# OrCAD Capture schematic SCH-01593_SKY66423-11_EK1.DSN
size B; title: SKY66423-11 EK1 915 MHz + LC ANT Filter; rev: C2; company: Skyworks Solutions; note: SCH-01593; note: 1145 Innovation Drive, 2nd Floor; note: Ottawa, Ontario   Canada
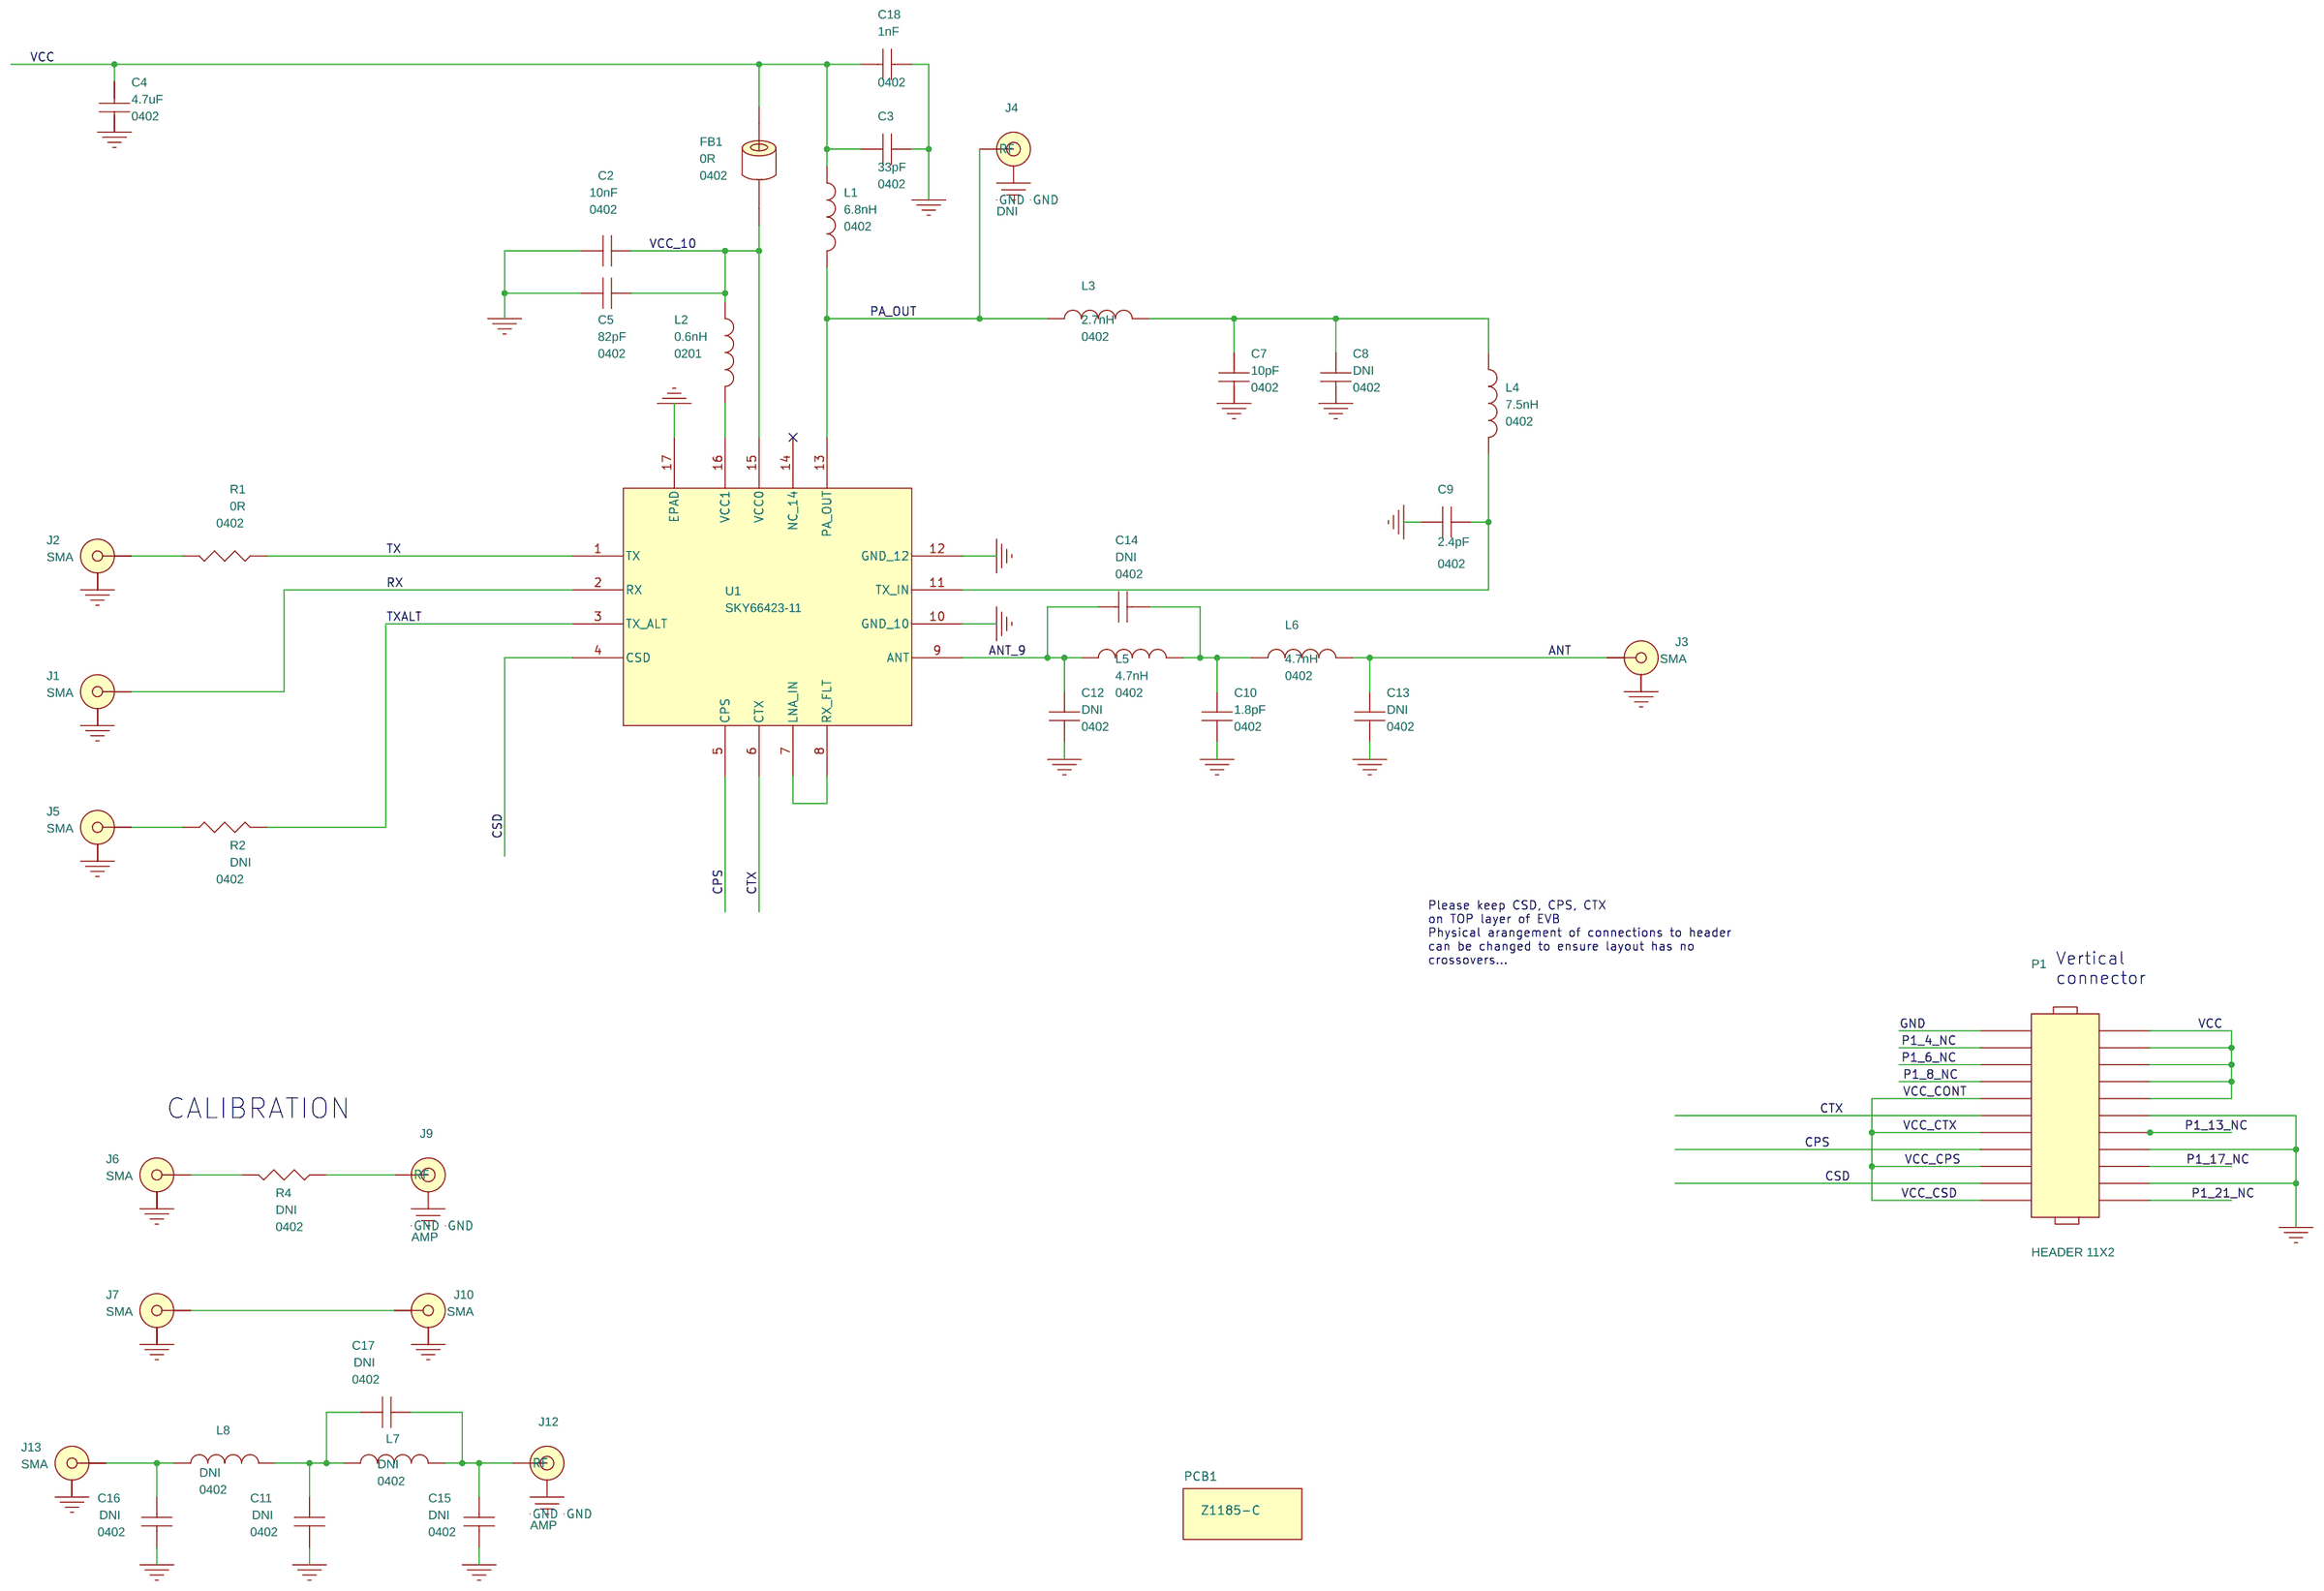
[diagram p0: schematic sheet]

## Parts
C2  10nF  [CAP_SMD_0402_1M0MX0M5M_B]
C3  33pF  [CAP_SMD_0402_1M0MX0M5M_B]
C4  4.7uF  [CAP_SMD_0402_1M0MX0M5M_B]
C5  82pF  [CAP_SMD_0402_1M0MX0M5M_B]
C7  10pF  [CAP_SMD_0402_1M0MX0M5M_B]
C8  DNI  [CAP_SMD_0402_1M0MX0M5M_B]
C9  2.4pF  [CAP_SMD_0402_1M0MX0M5M_B]
C10  1.8pF  [CAP_SMD_0402_1M0MX0M5M_B]
C11  DNI  [CAP_SMD_0402_1M0MX0M5M_B]
C12  DNI  [CAP_SMD_0402_1M0MX0M5M_B]
C13  DNI  [CAP_SMD_0402_1M0MX0M5M_B]
C14  DNI  [CAP_SMD_0402_1M0MX0M5M_B]
C15  DNI  [CAP_SMD_0402_1M0MX0M5M_B]
C16  DNI  [CAP_SMD_0402_1M0MX0M5M_B]
C17  DNI  [CAP_SMD_0402_1M0MX0M5M_B]
C18  1nF  [CAP_SMD_0402_1M0MX0M5M_B]
FB1  0R  [IND_SMD_0402_1M0MX0M5M_B]
J1  SMA  [SMA_END_B]
J2  SMA  [SMA_END_B]
J3  SMA  [SMA_END_B]
J4  DNI  [conn_amp_132134_10_V2]
J5  SMA  [SMA_END_B]
J6  SMA  [SMA_END_B]
J7  SMA  [SMA_END_B]
J9  AMP  [conn_amp_132134_10_V2]
J10  SMA  [SMA_END_B]
J12  AMP  [conn_amp_132134_10_V2]
J13  SMA  [SMA_END_B]
L1  6.8nH  [IND_SMD_0402_1M0MX0M5M_B]
L2  0.6nH  [ind_smd_0201_0m6mx0m3m_b]
L3  2.7nH  [IND_SMD_0402_1M0MX0M5M_B]
L4  7.5nH  [IND_SMD_0402_1M0MX0M5M_B]
L5  4.7nH  [IND_SMD_0402_1M0MX0M5M_B]
L6  4.7nH  [IND_SMD_0402_1M0MX0M5M_B]
L7  DNI  [IND_SMD_0402_1M0MX0M5M_B]
L8  DNI  [IND_SMD_0402_1M0MX0M5M_B]
P1  HEADER 11X2  [HDR_THRU_22P_11X2_100_ST_M]
PCB1  Z1185-C
R1  0R  [res_smd_0402_1m0mx0m5m_b]
R2  DNI  [res_smd_0402_1m0mx0m5m_b]
R4  DNI  [res_smd_0402_1m0mx0m5m_b]
U1  SKY66423-11  [SP01-D577-A]

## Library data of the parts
C2 = CAP_NP: CAP CER 10000PF 50V X7R 0402; MANUFACTURER: MURATA; MANUFACTURER_PN: GRM155R71H103KA88; PACKAGE: 0402
C3 = CAP_NP: CAP CER 33PF 50V C0G/NP0 0402; MANUFACTURER: MURATA; MANUFACTURER_PN: GRM1555C1H330JA01; PACKAGE: 0402
C4 = CAP_NP: CAP CER 4.7UF 10V X5R 0402; MANUFACTURER: MURATA; MANUFACTURER_PN: GRM155R61A475MEAA; PACKAGE: 0402
C5 = CAP_NP: CAP CER 82PF 50V C0G/NP0 0402; MANUFACTURER: MURATA; MANUFACTURER_PN: GRM1555C1H820JA01; PACKAGE: 0402
C7 = CAP_NP: CAP CER 10PF 25V C0G/NP0 0402; MANUFACTURER: MURATA; MANUFACTURER_PN: GRM1555C1E100JA01D; PACKAGE: 0402
C8 C14 = CAP_NP: PACKAGE: 0402
C9 = CAP_NP: CAP CER 2.4PF 50V C0G/NP0 0402; MANUFACTURER: MURATA; MANUFACTURER_PN: GRM1555C1H2R4CA01; PACKAGE: 0402
C10 = CAP_NP: CAP CER 1.8PF 50V C0G/NP0 0402; MANUFACTURER: MURATA; MANUFACTURER_PN: GRM1555C1H1R8CA01; PACKAGE: 0402
C11 C15-C17 = CAP_NP: BOM_IGNORE: TRUE; PACKAGE: 0402
C12 C13 = CAP_NP: MANUFACTURER: MURATA; PACKAGE: 0402
C18 = CAP_NP: CAP CER 1000PF 50V X7R 0402; MANUFACTURER: MURATA; MANUFACTURER_PN: GRM155R71H102KA01; PACKAGE: 0402
FB1 = FERRITE_BEAD: MANUFACTURER_PN: ERJ2GE0R00; PACKAGE: 0402
J1-J3 J5 = SMA_3pin: SMA End Launch Straight Jack Receptacle; Manufacturer: Johnson Components; Manufacturer_PN: 142-0701-851; PCBDESCRIPTION: SMA End Launch Straight Jack Receptacle; PCBMANUFACTURER: Johnson Components; PCBMANUFACTURER_PN: 142-0701-851; Package: end launch
J4 = SMA_3: CONN SMA JACK STR 50 OHM PCB; CLASS: IO; MANUFACTURER: AMPHENOL; PACKAGE: AMPHENOL_132134; Pic Spec: 615R54-021
J6 J7 J10 J13 = SMA_3pin: SMA End Launch Straight Jack Receptacle; BOM_IGNORE: TRUE; Manufacturer: Johnson Components; Manufacturer_PN: 142-0701-851; PCBDESCRIPTION: SMA End Launch Straight Jack Receptacle; PCBMANUFACTURER: Johnson Components; PCBMANUFACTURER_PN: 142-0701-851; Package: end launch
J9 J12 = SMA_3: CONN SMA JACK STR 50 OHM PCB; BOM_IGNORE: TRUE; CLASS: IO; MANUFACTURER: AMPHENOL; MANUFACTURER_PN: 132134; PACKAGE: AMPHENOL_132134; Pic Spec: 615R54-021
L1 = IND_7: FIXED IND 6.8NH 600MA 290 MOHM; MANUFACTURER: MURATA; MANUFACTURER_PN: LQW15AN6N8J00D; PACKAGE: 0402
L2 = IND_7: FIXED IND 0.6NH 850MA 70 MOHM; MANUFACTURER: MURATA; MANUFACTURER_PN: LQP03TN0N6B02D; PACKAGE: 0201
L3 = IND_1: FIXED IND 2.7NH 800MA 170 MOHM; MANUFACTURER: MURATA; MANUFACTURER_PN: LQG15HN2N7S02D; PACKAGE: 0402
L4 = IND_0: FIXED IND 7.5NH 500MA 310 MOHM; MANUFACTURER: MURATA; MANUFACTURER_PN: LQG15HN7N5J02; PACKAGE: 0402
L5 L6 = IND_2: FIXED IND 4.7NH 600MA 260 MOHM; MANUFACTURER: MURATA; MANUFACTURER_PN: LQG15HN4N7S02; PACKAGE: 0402
L7 L8 = IND_2: BOM_IGNORE: TRUE; MANUFACTURER: MURATA; MANUFACTURER_PN: LQG15HN5N6S02D; PACKAGE: 0402
P1 = HEADER_11X2: MANUFACTURER: MOLEX; MANUFACTURER_PN: 10-89-1221; PACKAGE: 11X2
PCB1 = PCB: EVB; MANUFACTURER: SKYWORKS SOLUTIONS
R1 = RESISTOR: RES SMD 0 OHM JUMPER 1/10W 0402; Manufacturer: Panasonic; Manufacturer_PN: ERJ2GE0R00; PART_NUMBER: ERJ2GE0R00; Package: 0402
R2 = RESISTOR: Package: 0402
R4 = RESISTOR: BOM_IGNORE: TRUE; Package: 0402
U1 = SKY13717_1: 860 to 930 MHz RF Front-End Module; MANUFACTURER: SKYWORKS SOLUTIONS; PACKAGE: MCM 16-PIN 3X3

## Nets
GND: C2.2 C3.1 C4.1 C5.2 C7.2 C8.2 C9.2 C10.2 C11.2 C12.2 C13.2 C15.2 C16.2 C18.1 J1.2(GND_SIGNAL) J1.3(GND_SIGNAL) J2.2(GND_SIGNAL) J2.3(GND_SIGNAL) J3.2(GND_SIGNAL) J3.3(GND_SIGNAL) J4.2(GND) J4.3(GND) J5.2(GND_SIGNAL) J5.3(GND_SIGNAL) J6.2(GND_SIGNAL) J6.3(GND_SIGNAL) J7.2(GND_SIGNAL) J7.3(GND_SIGNAL) J9.2(GND) J9.3(GND) J10.2(GND_SIGNAL) J10.3(GND_SIGNAL) J12.2(GND) J12.3(GND) J13.2(GND_SIGNAL) J13.3(GND_SIGNAL) P1.2 P1.11 P1.15 P1.19 U1.10(GND) U1.12(GND) U1.17(EPAD)
VCC: C3.2 C4.2 C18.2 FB1.1 L1.1 P1.1 P1.3 P1.5 P1.7 P1.9
VCC_10: C2.1 C5.1 FB1.2 L2.1 U1.15(VCC0)
VCC_CONT: P1.10 P1.14 P1.18 P1.22
ANT: C13.1 J3.1(SIG) L6.1
ANT_9: C12.1 C14.1 L5.2 U1.9(ANT)
CPS: P1.16 U1.5(CPS)
CSD: P1.20 U1.4(CSD)
CTX: P1.12 U1.6(CTX)
P1_4_NC: P1.4
P1_6_NC: P1.6
P1_8_NC: P1.8
P1_13_NC: P1.13
P1_17_NC: P1.17
P1_21_NC: P1.21
PA_OUT: J4.1(RF) L1.2 L3.2 U1.13(PA_OUT)
RX: J1.1(SIG) U1.2(RX)
TX: R1.1 U1.1(TX)
TXALT: R2.1 U1.3(TX_ALT)
N17610851: J2.1(SIG) R1.2
N17611136: U1.7(LNA_IN) U1.8(RX_FLT)
N17611175: J5.1(SIG) R2.2
N17627451: C7.1 C8.1 L3.1 L4.1
N17627472: C9.1 L4.2 U1.11(TX_IN)
N17628339: C10.1 C14.2 L5.1 L6.2
N17628678: J6.1(SIG) R4.2
N17628680: J7.1(SIG) J10.1(SIG)
N17628695: J9.1(RF) R4.1
N17628737: C11.1 C17.2 L7.1 L8.2
N17628745: C16.1 J13.1(SIG) L8.1
N17628747: C15.1 C17.1 J12.1(RF) L7.2
N17629100: L2.2 U1.16(VCC1)

Not connected (* = marked no-connect by the designer): U1 14(NC)*

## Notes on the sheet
- Please keep CSD, CPS, CTX
  on TOP layer of EVB
  Physical arangement of connections to header
  can be changed to ensure layout has no
  crossovers...
- Vertical
  connector
- CALIBRATION
